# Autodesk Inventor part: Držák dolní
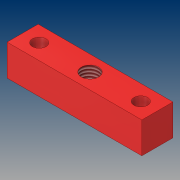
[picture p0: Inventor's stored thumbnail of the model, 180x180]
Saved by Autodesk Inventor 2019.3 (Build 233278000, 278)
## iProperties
Created: 2019-02
Part Number: Držák dolní
Material: Ocel, legovaná
Document SubType Name: Modeling
Designer: B-hon
Density: 7.73 g/cm^3
Appearance: Světle červená
Author: B-hon
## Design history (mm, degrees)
sketch "Náčrt1"
  geometry: L1 (-32.5, 7.5)-(32.5, 7.5); L2 (32.5, 7.5)-(32.5, -7.5); L3 (32.5, -7.5)-(-32.5, -7.5); L4 (-32.5, -7.5)-(-32.5, 7.5); L5 (-32.5, 7.5)-(32.5, -7.5); L6 (32.5, 7.5)-(-32.5, -7.5); 1 further point
  constraints: 12 end point, 2 midpoint, 2 parallel, 1 horizontal, 1 perpendicular
  dimensions: "d0" = 65 distance of L2.end L3.end; "d1" = 15 distance of L1.end L2.end
extrude "Vysunutí1" new body sketch "Náčrt1" stored distance "d2" = 15; taper "d3" = 0 deg
sketch "Náčrt2"
  geometry: L1 (65, 0)-(65, 15) reference; L2 (65, 0)-(0, 0) reference; L3 (0, 15)-(0, 0) reference; 3 further points
  dimensions: "d4" = 8 distance from line of L1 point (57, 7.5); "d5" = 7.5 distance from line of L2 point (57, 7.5); "d6" = 8 distance from line of L3 point (8, 7.5); "d7" = 7.5 distance from line of L2 point (8, 7.5)
hole "Díra1" sketch "Náčrt2" at (57, 7.5), (8, 7.5) diameter "d8" = 6.6; stored, may be unused: countersink angle "d12" = 90 deg, drill point angle "d14" = 118 deg; dims "d9" = 6, "d10" = 4, "d11" = 2, "d13" = 8
sketch "Náčrt3"
  geometry: L1 (65, 0)-(0, 0) reference; L2 (65, 0)-(65, 15) reference; 2 further points
  dimensions: "d15" = 7.5 distance from line of L1 point (32.5, 7.5); "d16" = 32.5 distance from line of L2 point (32.5, 7.5)
hole "Díra2" sketch "Náčrt3" at (32.5, 7.5) diameter "d17" = 8.376; stored, may be unused: countersink angle "d21" = 90 deg, drill point angle "d23" = 118 deg; dims "d18" = 20, "d19" = 4, "d20" = 2, "d22" = 27.3
node "Těleso1"
